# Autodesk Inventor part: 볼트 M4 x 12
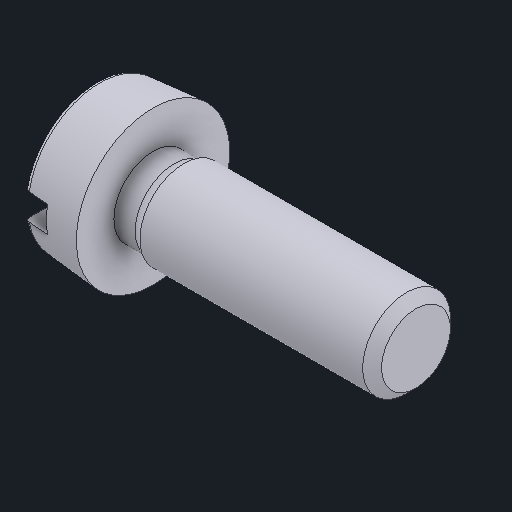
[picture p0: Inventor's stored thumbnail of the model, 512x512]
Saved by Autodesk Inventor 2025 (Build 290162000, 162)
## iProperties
Created: 2025-08
Part Number: 볼트 M4 x 12
Material: 강철, 연강
Description: 6각머리 태핑 나사
Document SubType Name: Modeling
Designer: infra006
Density: 7.85 g/cm^3
Appearance: 기본값
Author: jhkim
Sending System: Autodesk Inventor 2026
Preprocessor: ST-DEVELOPER v20.1
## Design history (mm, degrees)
feature "Solid1"
node "솔리드1"
